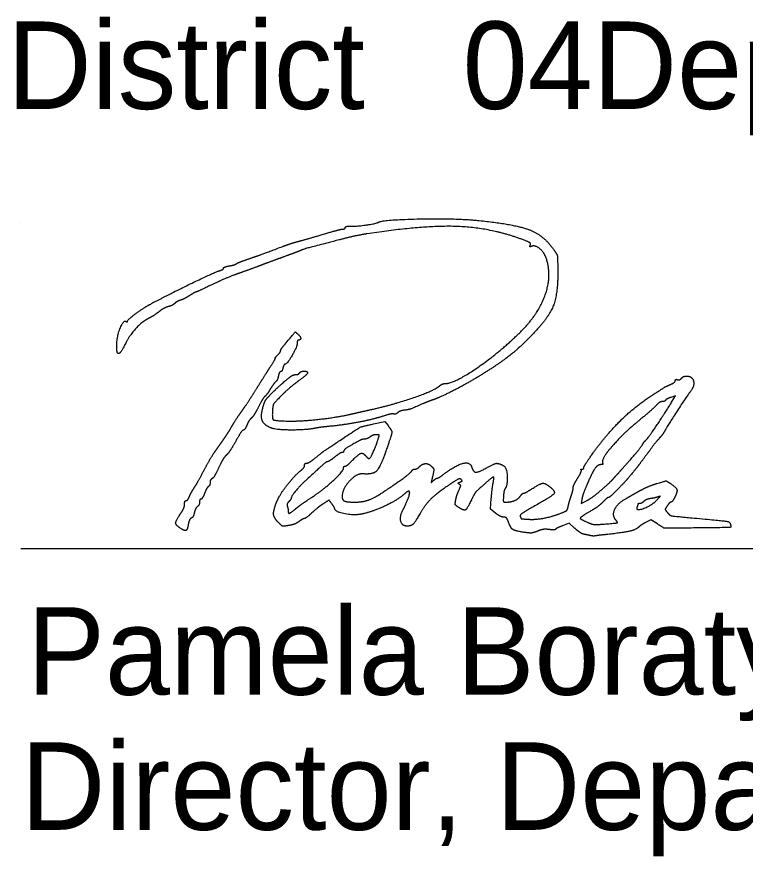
# Model space of a CAD drawing. Extents: x -6.4 to 34, y -4.2 to 22.
# Drawn here: x 24.543 to 25.708, y 7.34 to 8.682 of the extents above; entities that cross this region are included whole.
import ezdxf

# ---------------------------------------------------------------- set-up
doc = ezdxf.new("R2010")
doc.units = 0
for name, color, linetype in [('Default', 7, 'Continuous'), ('SH_Data', 7, 'Continuous'), ('SH_Text', 7, 'Continuous')]:
    doc.layers.add(name, color=color, linetype=linetype)

msp = doc.modelspace()

# ---------------------------------------------------------------- linework, layer by layer
at = {"layer": 'Default'}
for points in [[(25.5912, 8.0673), (25.5966, 8.0762), (25.5893, 8.0736)], [(25.1139, 8.0311), (25.1319, 8.0352), (25.1366, 8.029)], [(25.3089, 7.8883), (25.3005, 7.8946), (25.302, 7.9117)], [(25.4469, 7.9103), (25.4458, 7.9038), (25.4545, 7.9083)], [(25.4358, 7.864), (25.4267, 7.8723), (25.4161, 7.8682)], [(25.5677, 7.871), (25.5571, 7.8778), (25.5487, 7.8733)]]:
    msp.add_lwpolyline(points, dxfattribs=at)
for points in [[(25.0773, 8.3475), (25.0869, 8.3472), (25.1179, 8.3516), (25.1213, 8.3537)], [(25.1213, 8.3537), (25.1281, 8.3579), (25.2451, 8.3602), (25.2795, 8.3568)], [(25.2795, 8.3568), (25.3388, 8.3509), (25.3863, 8.3327), (25.4021, 8.3096)], [(25.0316, 8.3341), (25.0477, 8.3389), (25.0625, 8.3428), (25.0646, 8.3428)], [(25.0646, 8.3428), (25.0666, 8.3428), (25.0683, 8.3439), (25.0683, 8.3452)], [(25.0683, 8.3452), (25.0683, 8.3466), (25.0724, 8.3476), (25.0773, 8.3475)], [(25.352, 8.326), (25.3015, 8.345), (25.1935, 8.349), (25.1031, 8.3352)], [(24.9927, 8.323), (24.998, 8.3243), (25.0155, 8.3293), (25.0316, 8.3341)], [(25.1031, 8.3352), (25.0939, 8.3338), (25.0739, 8.3295), (25.0587, 8.3255)], [(24.9123, 8.2945), (24.927, 8.2996), (24.9335, 8.302), (24.9687, 8.3151)], [(24.9687, 8.3151), (24.9767, 8.3181), (24.9875, 8.3216), (24.9927, 8.323)], [(25.0587, 8.3255), (25.0077, 8.3123), (25.0034, 8.3111), (24.9927, 8.3068)], [(25.3643, 8.3174), (25.3653, 8.3199), (25.3619, 8.3223), (25.352, 8.326)], [(25.3667, 8.3153), (25.3641, 8.3143), (25.3634, 8.315), (25.3643, 8.3174)], [(25.3901, 8.2954), (25.3869, 8.3052), (25.3724, 8.3175), (25.3667, 8.3153)], [(24.9927, 8.3068), (24.9901, 8.3057), (24.9798, 8.3019), (24.9699, 8.2983)], [(25.4021, 8.3096), (25.4071, 8.3024), (25.408, 8.298), (25.4083, 8.2802)], [(24.8829, 8.2839), (24.8879, 8.2848), (24.893, 8.2864), (24.8943, 8.2874)], [(24.8943, 8.2874), (24.8957, 8.2883), (24.9038, 8.2916), (24.9123, 8.2945)], [(24.9699, 8.2983), (24.96, 8.2947), (24.9449, 8.2891), (24.9363, 8.2859)], [(25.3446, 8.1742), (25.3756, 8.2036), (25.3994, 8.2672), (25.3901, 8.2954)], [(24.7563, 8.2224), (24.7866, 8.2386), (24.8602, 8.2742), (24.8685, 8.2767)], [(24.9003, 8.2727), (24.8891, 8.2688), (24.8688, 8.2602), (24.8551, 8.2537)], [(24.8685, 8.2767), (24.8715, 8.2776), (24.8739, 8.2792), (24.8739, 8.2802)], [(24.8739, 8.2802), (24.8739, 8.2813), (24.878, 8.283), (24.8829, 8.2839)], [(24.9363, 8.2859), (24.9278, 8.2826), (24.9116, 8.2767), (24.9003, 8.2727)], [(25.4083, 8.2802), (25.4091, 8.2394), (25.393, 8.1997), (25.3636, 8.1698)], [(24.8551, 8.2537), (24.8415, 8.2472), (24.8298, 8.242), (24.8293, 8.242)], [(24.8193, 8.2363), (24.8144, 8.2332), (24.8077, 8.2298), (24.8044, 8.2288)], [(24.8293, 8.242), (24.8287, 8.242), (24.8242, 8.2394), (24.8193, 8.2363)], [(24.7203, 8.1957), (24.7203, 8.1979), (24.7457, 8.2167), (24.7563, 8.2224)], [(24.7953, 8.2236), (24.7935, 8.2218), (24.7891, 8.2197), (24.7856, 8.2188)], [(24.8044, 8.2288), (24.8012, 8.2278), (24.7971, 8.2254), (24.7953, 8.2236)], [(24.7707, 8.2107), (24.7661, 8.2071), (24.759, 8.2025), (24.7548, 8.2004)], [(24.7856, 8.2188), (24.782, 8.2179), (24.7754, 8.2143), (24.7707, 8.2107)], [(24.7032, 8.1579), (24.7033, 8.1711), (24.7139, 8.1976), (24.718, 8.1951)], [(24.718, 8.1951), (24.7193, 8.1943), (24.7203, 8.1946), (24.7203, 8.1957)], [(24.7548, 8.2004), (24.7444, 8.1951), (24.7245, 8.1742), (24.7183, 8.1621)], [(24.9705, 8.1568), (24.9891, 8.1789), (24.9884, 8.1784), (24.9925, 8.175)], [(24.9925, 8.175), (24.9967, 8.1714), (24.9977, 8.1652), (24.9939, 8.1652)], [(25.2279, 8.0956), (25.242, 8.0956), (25.3101, 8.1415), (25.3446, 8.1742)], [(25.3636, 8.1698), (25.345, 8.1509), (25.3126, 8.126), (25.2821, 8.1072)], [(24.7045, 8.1442), (24.7037, 8.145), (24.7031, 8.1511), (24.7032, 8.1579)], [(24.7183, 8.1621), (24.7117, 8.1492), (24.7064, 8.1423), (24.7045, 8.1442)], [(24.9651, 8.1481), (24.9651, 8.1494), (24.9676, 8.1532), (24.9705, 8.1568)], [(24.9915, 8.1601), (24.9915, 8.1545), (24.9756, 8.1268), (24.9724, 8.1268)], [(24.9939, 8.1652), (24.9926, 8.1652), (24.9915, 8.1629), (24.9915, 8.1601)], [(24.9566, 8.1364), (24.956, 8.1364), (24.9577, 8.1385), (24.9603, 8.1412)], [(24.9603, 8.1412), (24.963, 8.1438), (24.9651, 8.1469), (24.9651, 8.1481)], [(24.9476, 8.1207), (24.9531, 8.1293), (24.9572, 8.1364), (24.9566, 8.1364)], [(24.9724, 8.1268), (24.9713, 8.1268), (24.9698, 8.1241), (24.9689, 8.1208)], [(24.9255, 8.0857), (24.9321, 8.0963), (24.9421, 8.1121), (24.9476, 8.1207)], [(24.9653, 8.1148), (24.9641, 8.1148), (24.9624, 8.1115), (24.9615, 8.1076)], [(24.9689, 8.1208), (24.9681, 8.1175), (24.9665, 8.1148), (24.9653, 8.1148)], [(24.9891, 8.11), (24.9916, 8.11), (24.9943, 8.111), (24.9951, 8.1124)], [(25.0083, 8.1127), (25.0083, 8.1116), (25.0016, 8.1057), (24.9933, 8.0996)], [(24.9951, 8.1124), (24.9969, 8.1153), (25.0083, 8.1156), (25.0083, 8.1127)], [(24.9576, 8.099), (24.9564, 8.0982), (24.9526, 8.093), (24.9492, 8.0876)], [(24.9567, 8.0858), (24.9724, 8.1004), (24.9852, 8.11), (24.9891, 8.11)], [(24.9615, 8.1076), (24.9607, 8.1036), (24.9589, 8.0998), (24.9576, 8.099)], [(24.9933, 8.0996), (24.9851, 8.0935), (24.9726, 8.0826), (24.9655, 8.0755)], [(25.2821, 8.1072), (25.2629, 8.0953), (25.2216, 8.0743), (25.2075, 8.0692)], [(25.5885, 8.0942), (25.5928, 8.0961), (25.5963, 8.099), (25.5963, 8.1005)], [(25.5963, 8.1005), (25.5963, 8.102), (25.5979, 8.1027), (25.5998, 8.102)], [(25.5998, 8.102), (25.6016, 8.1012), (25.6045, 8.1022), (25.6061, 8.1041)], [(25.6061, 8.1041), (25.6076, 8.106), (25.6113, 8.1076), (25.6142, 8.1076)], [(25.6142, 8.1076), (25.6237, 8.1076), (25.6274, 8.0915), (25.62, 8.0825)], [(24.9038, 8.0527), (24.9091, 8.0602), (24.9189, 8.075), (24.9255, 8.0857)], [(24.9354, 8.0512), (24.9381, 8.0642), (24.9443, 8.0742), (24.9567, 8.0858)], [(24.9492, 8.0876), (24.9458, 8.0821), (24.9417, 8.0765), (24.94, 8.0751)], [(25.1079, 8.0536), (25.1449, 8.0618), (25.2111, 8.0847), (25.2197, 8.0922)], [(25.2197, 8.0922), (25.2218, 8.0941), (25.2255, 8.0956), (25.2279, 8.0956)], [(25.5596, 8.0772), (25.5785, 8.0894), (25.5803, 8.0905), (25.5885, 8.0942)], [(24.94, 8.0751), (24.9383, 8.0738), (24.9337, 8.0662), (24.9297, 8.0582)], [(24.9655, 8.0755), (24.9548, 8.0645), (24.9527, 8.0608), (24.9521, 8.0526)], [(25.4649, 7.9846), (25.4872, 8.0155), (25.5322, 8.0595), (25.5596, 8.0772)], [(25.62, 8.0825), (25.6159, 8.0775), (25.583, 8.0271), (25.5799, 8.0209)], [(25.5893, 8.0736), (25.5852, 8.0722), (25.5813, 8.0701), (25.5806, 8.0689)], [(24.9297, 8.0582), (24.9256, 8.0502), (24.9206, 8.0422), (24.9184, 8.0404)], [(25.1919, 8.063), (25.1748, 8.0556), (25.1699, 8.0539), (25.1633, 8.0531)], [(25.2075, 8.0692), (25.2029, 8.0676), (25.1959, 8.0648), (25.1919, 8.063)], [(25.5664, 8.0614), (25.5637, 8.0584), (25.5513, 8.0473), (25.5387, 8.0368)], [(25.5485, 8.0044), (25.5513, 8.0063), (25.5795, 8.0478), (25.5912, 8.0673)], [(25.5753, 8.0668), (25.5731, 8.0668), (25.5691, 8.0643), (25.5664, 8.0614)], [(25.5806, 8.0689), (25.5799, 8.0677), (25.5775, 8.0668), (25.5753, 8.0668)], [(24.8871, 8.0272), (24.8909, 8.0338), (24.8984, 8.0453), (24.9038, 8.0527)], [(24.9507, 8.0243), (24.9403, 8.0282), (24.9332, 8.0407), (24.9354, 8.0512)], [(24.9521, 8.0526), (24.9513, 8.0392), (24.9553, 8.0363), (24.9759, 8.0357)], [(24.9759, 8.0357), (24.9952, 8.0352), (25.053, 8.0413), (25.0743, 8.0461)], [(25.0743, 8.0461), (25.0823, 8.0479), (25.0974, 8.0513), (25.1079, 8.0536)], [(25.1457, 8.0469), (25.1441, 8.0475), (25.136, 8.0458), (25.1277, 8.0431)], [(25.1525, 8.0491), (25.1504, 8.0473), (25.1474, 8.0463), (25.1457, 8.0469)], [(25.1633, 8.0531), (25.1595, 8.0527), (25.1546, 8.0509), (25.1525, 8.0491)], [(24.9184, 8.0404), (24.9162, 8.0386), (24.913, 8.0335), (24.9111, 8.0291)], [(25.1277, 8.0431), (25.1113, 8.0379), (25.0662, 8.0294), (25.0424, 8.0271)], [(25.0599, 8.0047), (25.0916, 8.0257), (25.093, 8.0264), (25.1139, 8.0311)], [(25.5387, 8.0368), (25.5191, 8.0203), (25.5074, 8.0089), (25.4907, 7.99)], [(24.874, 8.0065), (24.8773, 8.0113), (24.8832, 8.0206), (24.8871, 8.0272)], [(24.9054, 8.0212), (24.9041, 8.0212), (24.8987, 8.0133), (24.8934, 8.0036)], [(24.9111, 8.0291), (24.9093, 8.0247), (24.9067, 8.0212), (24.9054, 8.0212)], [(25.022, 8.0245), (25.0083, 8.0214), (24.9588, 8.0213), (24.9507, 8.0243)], [(25.0424, 8.0271), (25.034, 8.0263), (25.0249, 8.0251), (25.022, 8.0245)], [(25.1366, 8.029), (25.1432, 8.0202), (25.1431, 8.0154), (25.1353, 7.9928)], [(25.5799, 8.0209), (25.5781, 8.0174), (25.5742, 8.012), (25.5712, 8.0087)], [(24.8605, 7.9873), (24.8646, 7.9931), (24.8707, 8.0018), (24.874, 8.0065)], [(25.0207, 7.9768), (25.0344, 7.9878), (25.0325, 7.9864), (25.0599, 8.0047)], [(25.0993, 8.0068), (25.0971, 8.0068), (25.0927, 8.0053), (25.0896, 8.0036)], [(25.1081, 8.0103), (25.1055, 8.0083), (25.1016, 8.0068), (25.0993, 8.0068)], [(25.1066, 7.9756), (25.1084, 7.9756), (25.1181, 7.9967), (25.1213, 8.0074)], [(25.118, 8.0139), (25.1151, 8.0138), (25.1106, 8.0122), (25.1081, 8.0103)], [(25.1213, 8.0074), (25.123, 8.0131), (25.1225, 8.0139), (25.118, 8.0139)], [(25.5445, 7.9992), (25.5457, 8.0014), (25.5475, 8.0037), (25.5485, 8.0044)], [(25.5712, 8.0087), (25.5683, 8.0055), (25.5593, 7.9942), (25.5515, 7.9835)], [(24.8934, 8.0036), (24.888, 7.9939), (24.8814, 7.9839), (24.8785, 7.9814)], [(25.0896, 8.0036), (25.0752, 7.9957), (25.0659, 7.9893), (25.0659, 7.9873)], [(25.1353, 7.9928), (25.1251, 7.9629), (25.1131, 7.9498), (25.0971, 7.9512)], [(25.5132, 7.9614), (25.5286, 7.9785), (25.5421, 7.9949), (25.5445, 7.9992)], [(24.8416, 7.9552), (24.8479, 7.967), (24.8564, 7.9815), (24.8605, 7.9873)], [(24.8785, 7.9814), (24.8757, 7.9788), (24.8701, 7.9697), (24.8662, 7.9612)], [(25.0515, 7.978), (25.0465, 7.974), (25.0415, 7.9707), (25.0404, 7.9707)], [(25.0633, 7.9852), (25.0618, 7.9852), (25.0565, 7.9819), (25.0515, 7.978)], [(25.0659, 7.9873), (25.0659, 7.9861), (25.0647, 7.9852), (25.0633, 7.9852)], [(25.0803, 7.9732), (25.0905, 7.9833), (25.097, 7.9851), (25.1019, 7.9792)], [(25.1019, 7.9792), (25.1036, 7.9772), (25.1057, 7.9756), (25.1066, 7.9756)], [(25.4499, 7.9613), (25.4499, 7.9627), (25.4567, 7.9732), (25.4649, 7.9846)], [(25.4907, 7.99), (25.4849, 7.9834), (25.4786, 7.9705), (25.4801, 7.9681)], [(25.5515, 7.9835), (25.5436, 7.9729), (25.5359, 7.9627), (25.5344, 7.9609)], [(24.9981, 7.9571), (25.0011, 7.9595), (25.0035, 7.963), (25.0035, 7.9649)], [(25.0035, 7.9649), (25.0035, 7.9668), (25.005, 7.9684), (25.0069, 7.9684)], [(25.0404, 7.9707), (25.0385, 7.9707), (25.03, 7.9635), (25.0047, 7.9402)], [(25.0069, 7.9684), (25.0088, 7.9684), (25.015, 7.9721), (25.0207, 7.9768)], [(25.0683, 7.9636), (25.0697, 7.9636), (25.0751, 7.9679), (25.0803, 7.9732)], [(25.1871, 7.9627), (25.1921, 7.9676), (25.202, 7.9677), (25.207, 7.9627)], [(25.2251, 7.9501), (25.2453, 7.9653), (25.2681, 7.9709), (25.271, 7.9614)], [(25.2948, 7.961), (25.3068, 7.9677), (25.314, 7.9684), (25.3222, 7.9638)], [(25.4778, 7.966), (25.4715, 7.966), (25.4619, 7.9508), (25.4499, 7.9216)], [(25.4801, 7.9681), (25.4808, 7.9669), (25.4798, 7.966), (25.4778, 7.966)], [(24.8261, 7.9276), (24.8283, 7.9309), (24.8353, 7.9433), (24.8416, 7.9552)], [(24.8662, 7.9612), (24.8623, 7.9526), (24.8576, 7.9447), (24.8557, 7.9436)], [(24.96, 7.9089), (24.9645, 7.9193), (24.9878, 7.9488), (24.9981, 7.9571)], [(25.0199, 7.917), (25.0354, 7.9274), (25.0659, 7.9561), (25.0659, 7.9604)], [(25.0971, 7.9512), (25.0867, 7.9521), (25.0635, 7.9267), (25.0635, 7.9144)], [(25.0659, 7.9604), (25.0659, 7.9621), (25.067, 7.9636), (25.0683, 7.9636)], [(25.1319, 7.9239), (25.1505, 7.9362), (25.1729, 7.9529), (25.1747, 7.9557)], [(25.1747, 7.9557), (25.1757, 7.9574), (25.1781, 7.9588), (25.1799, 7.9588)], [(25.1799, 7.9588), (25.1817, 7.9588), (25.1849, 7.9605), (25.1871, 7.9627)], [(25.207, 7.9627), (25.2101, 7.9596), (25.2104, 7.9571), (25.2083, 7.948)], [(25.271, 7.9614), (25.2735, 7.9538), (25.2815, 7.9537), (25.2948, 7.961)], [(25.3222, 7.9638), (25.3266, 7.9613), (25.3283, 7.9333), (25.3244, 7.9281)], [(25.4402, 7.9445), (25.444, 7.9507), (25.4466, 7.9565), (25.4458, 7.9573)], [(25.4458, 7.9573), (25.445, 7.9581), (25.4456, 7.9588), (25.4471, 7.9588)], [(25.4471, 7.9588), (25.4487, 7.9588), (25.4499, 7.9599), (25.4499, 7.9613)], [(25.4976, 7.9439), (25.5008, 7.9475), (25.5078, 7.9553), (25.5132, 7.9614)], [(25.5344, 7.9609), (25.5211, 7.9444), (25.5166, 7.9393), (25.5047, 7.9271)], [(24.8523, 7.9372), (24.8523, 7.9347), (24.8512, 7.9319), (24.8498, 7.9311)], [(24.8557, 7.9436), (24.8538, 7.9426), (24.8523, 7.9397), (24.8523, 7.9372)], [(25.0047, 7.9402), (24.9956, 7.9318), (24.9819, 7.9148), (24.9819, 7.9118)], [(25.2083, 7.948), (25.2059, 7.9377), (25.206, 7.9372), (25.2098, 7.9407)], [(25.2098, 7.9407), (25.2121, 7.9427), (25.2147, 7.9444), (25.2157, 7.9444)], [(25.2157, 7.9444), (25.2167, 7.9444), (25.2209, 7.9469), (25.2251, 7.9501)], [(25.2538, 7.9423), (25.252, 7.9441), (25.2461, 7.9413), (25.2336, 7.9328)], [(25.2509, 7.9346), (25.2487, 7.936), (25.249, 7.9369), (25.2521, 7.9381)], [(25.2521, 7.9381), (25.2551, 7.9392), (25.2556, 7.9405), (25.2538, 7.9423)], [(25.2949, 7.9382), (25.279, 7.9242), (25.2752, 7.9198), (25.2697, 7.9084)], [(25.305, 7.9366), (25.3068, 7.946), (25.3042, 7.9464), (25.2949, 7.9382)], [(25.4331, 7.9297), (25.4331, 7.9315), (25.4363, 7.9382), (25.4402, 7.9445)], [(25.4775, 7.9251), (25.4855, 7.9319), (25.4945, 7.9404), (25.4976, 7.9439)], [(25.5668, 7.9358), (25.5809, 7.94), (25.5821, 7.94), (25.5879, 7.9362)], [(24.8193, 7.915), (24.8208, 7.9186), (24.8239, 7.9243), (24.8261, 7.9276)], [(24.8498, 7.9311), (24.8485, 7.9302), (24.8456, 7.9253), (24.8436, 7.9201)], [(25.0835, 7.906), (25.0965, 7.906), (25.1156, 7.913), (25.1319, 7.9239)], [(25.2336, 7.9328), (25.2138, 7.9194), (25.1966, 7.9023), (25.1883, 7.888)], [(25.2451, 7.9092), (25.2459, 7.9133), (25.2482, 7.9204), (25.2502, 7.9248)], [(25.2502, 7.9248), (25.2531, 7.9311), (25.2532, 7.9332), (25.2509, 7.9346)], [(25.302, 7.9117), (25.3028, 7.9211), (25.3041, 7.9323), (25.305, 7.9366)], [(25.3244, 7.9281), (25.3232, 7.9265), (25.3218, 7.9208), (25.3215, 7.9155)], [(25.354, 7.9204), (25.3552, 7.9204), (25.3613, 7.9236), (25.3675, 7.9276)], [(25.3957, 7.9305), (25.4054, 7.9229), (25.3986, 7.915), (25.367, 7.8973)], [(25.3675, 7.9276), (25.3805, 7.9358), (25.3881, 7.9366), (25.3957, 7.9305)], [(25.4296, 7.9156), (25.4316, 7.9215), (25.4332, 7.9279), (25.4331, 7.9297)], [(25.4545, 7.9083), (25.4592, 7.9107), (25.4696, 7.9183), (25.4775, 7.9251)], [(25.5047, 7.9271), (25.4972, 7.9194), (25.4902, 7.9132), (25.4891, 7.9132)], [(25.5375, 7.9231), (25.5455, 7.9276), (25.5586, 7.9333), (25.5668, 7.9358)], [(25.5879, 7.9362), (25.5975, 7.9299), (25.6, 7.9225), (25.5953, 7.9135)], [(24.814, 7.9084), (24.8153, 7.9084), (24.8177, 7.9113), (24.8193, 7.915)], [(24.8377, 7.9108), (24.8365, 7.9108), (24.8355, 7.9087), (24.8355, 7.9062)], [(24.8436, 7.9201), (24.8415, 7.915), (24.8388, 7.9108), (24.8377, 7.9108)], [(24.9819, 7.9118), (24.9819, 7.911), (24.9802, 7.9087), (24.9782, 7.9067)], [(24.9883, 7.8946), (24.9959, 7.9007), (25.0011, 7.9045), (25.0199, 7.917)], [(25.0635, 7.9144), (25.0635, 7.9093), (25.0714, 7.906), (25.0835, 7.906)], [(25.1639, 7.9197), (25.1543, 7.9106), (25.1156, 7.8918), (25.0971, 7.8873)], [(25.161, 7.894), (25.1651, 7.9016), (25.1715, 7.9179), (25.1715, 7.9206)], [(25.1715, 7.9206), (25.1715, 7.9237), (25.1676, 7.9232), (25.1639, 7.9197)], [(25.3215, 7.9155), (25.321, 7.908), (25.3217, 7.906), (25.3248, 7.906)], [(25.3248, 7.906), (25.3331, 7.906), (25.3451, 7.9108), (25.3484, 7.9155)], [(25.3484, 7.9155), (25.3503, 7.9182), (25.3528, 7.9204), (25.354, 7.9204)], [(25.4249, 7.8985), (25.4255, 7.9019), (25.4277, 7.9096), (25.4296, 7.9156)], [(25.4499, 7.9216), (25.4488, 7.9189), (25.4474, 7.9138), (25.4469, 7.9103)], [(25.4891, 7.9132), (25.488, 7.9132), (25.4842, 7.91), (25.4806, 7.9062)], [(25.5009, 7.8777), (25.4949, 7.8851), (25.5046, 7.9049), (25.518, 7.9121)], [(25.518, 7.9121), (25.5208, 7.9136), (25.5296, 7.9186), (25.5375, 7.9231)], [(25.5569, 7.9117), (25.5531, 7.9112), (25.5481, 7.9091), (25.5459, 7.9072)], [(25.5687, 7.9144), (25.5661, 7.9134), (25.5608, 7.9122), (25.5569, 7.9117)], [(25.5663, 7.9089), (25.5718, 7.9145), (25.5724, 7.9158), (25.5687, 7.9144)], [(25.5953, 7.9135), (25.5932, 7.9093), (25.5905, 7.906), (25.5893, 7.906)], [(24.8057, 7.8885), (24.8089, 7.8932), (24.8115, 7.8996), (24.8115, 7.9027)], [(24.8115, 7.9027), (24.8115, 7.9058), (24.8126, 7.9084), (24.814, 7.9084)], [(24.8321, 7.8989), (24.8302, 7.8973), (24.8279, 7.8928), (24.8271, 7.8888)], [(24.8355, 7.9062), (24.8355, 7.9038), (24.834, 7.9005), (24.8321, 7.8989)], [(24.9617, 7.8732), (24.9541, 7.8808), (24.9535, 7.8936), (24.96, 7.9089)], [(24.9782, 7.9067), (24.9761, 7.9046), (24.9751, 7.9014), (24.9758, 7.8994)], [(24.9758, 7.8994), (24.9765, 7.8975), (24.9771, 7.8944), (24.9771, 7.8926)], [(25.0356, 7.9048), (25.0274, 7.8994), (25.0249, 7.8974), (25.0137, 7.8874)], [(25.0469, 7.9034), (25.0425, 7.9092), (25.0424, 7.9092), (25.0356, 7.9048)], [(25.0515, 7.896), (25.0514, 7.8969), (25.0494, 7.9002), (25.0469, 7.9034)], [(25.2497, 7.8976), (25.2448, 7.9009), (25.244, 7.9029), (25.2451, 7.9092)], [(25.2697, 7.9084), (25.2631, 7.8947), (25.2582, 7.8921), (25.2497, 7.8976)], [(25.367, 7.8973), (25.3538, 7.8898), (25.3475, 7.885), (25.3484, 7.8828)], [(25.4122, 7.8878), (25.421, 7.8912), (25.4239, 7.8937), (25.4249, 7.8985)], [(25.4806, 7.9062), (25.4769, 7.9024), (25.4688, 7.8963), (25.4626, 7.8926)], [(25.5349, 7.8978), (25.5324, 7.8913), (25.5579, 7.9002), (25.5663, 7.9089)], [(25.5363, 7.9025), (25.5363, 7.902), (25.5357, 7.8999), (25.5349, 7.8978)], [(25.5391, 7.9036), (25.5376, 7.9036), (25.5363, 7.9031), (25.5363, 7.9025)], [(25.5459, 7.9072), (25.5437, 7.9052), (25.5407, 7.9036), (25.5391, 7.9036)], [(25.5835, 7.9001), (25.58, 7.8948), (25.58, 7.8939), (25.5838, 7.8892)], [(25.5893, 7.906), (25.5882, 7.906), (25.5856, 7.9033), (25.5835, 7.9001)], [(24.804, 7.8648), (24.797, 7.8696), (24.7975, 7.8763), (24.8057, 7.8885)], [(24.8271, 7.8888), (24.8262, 7.8849), (24.8241, 7.8811), (24.8223, 7.8804)], [(24.9771, 7.8926), (24.9771, 7.8877), (24.9806, 7.8883), (24.9883, 7.8946)], [(25.0137, 7.8874), (25.0089, 7.8831), (25.004, 7.8796), (25.0029, 7.8796)], [(25.0971, 7.8873), (25.0843, 7.8842), (25.0517, 7.8904), (25.0515, 7.896)], [(25.1677, 7.8676), (25.1593, 7.8676), (25.1553, 7.8834), (25.161, 7.894)], [(25.1883, 7.888), (25.1801, 7.8738), (25.1738, 7.8676), (25.1677, 7.8676)], [(25.3219, 7.882), (25.3193, 7.882), (25.3134, 7.8848), (25.3089, 7.8883)], [(25.3623, 7.8785), (25.3729, 7.8779), (25.399, 7.8828), (25.4122, 7.8878)], [(25.4626, 7.8926), (25.4446, 7.8822), (25.4436, 7.8789), (25.4565, 7.8734)], [(25.5838, 7.8892), (25.5875, 7.8847), (25.5925, 7.8837), (25.6263, 7.8805)], [(24.8177, 7.8712), (24.8159, 7.8615), (24.8117, 7.8595), (24.804, 7.8648)], [(24.8223, 7.8804), (24.8206, 7.8798), (24.8185, 7.8756), (24.8177, 7.8712)], [(24.9779, 7.8685), (24.9692, 7.8672), (24.9671, 7.8678), (24.9617, 7.8732)], [(24.9944, 7.8748), (24.9909, 7.8722), (24.9834, 7.8694), (24.9779, 7.8685)], [(25.0029, 7.8796), (25.0018, 7.8796), (24.998, 7.8774), (24.9944, 7.8748)], [(25.3294, 7.8742), (25.3275, 7.8793), (25.325, 7.882), (25.3219, 7.882)], [(25.3548, 7.8576), (25.3397, 7.86), (25.3329, 7.8645), (25.3294, 7.8742)], [(25.3484, 7.8828), (25.3497, 7.8794), (25.3504, 7.8792), (25.3623, 7.8785)], [(25.4565, 7.8734), (25.4634, 7.8704), (25.4698, 7.8699), (25.4833, 7.8709)], [(25.4833, 7.8709), (25.5029, 7.8725), (25.5046, 7.8732), (25.5009, 7.8777)], [(25.5487, 7.8733), (25.5441, 7.8708), (25.5388, 7.8673), (25.537, 7.8654)], [(25.6143, 7.8645), (25.5786, 7.8642), (25.5783, 7.8642), (25.5677, 7.871)], [(25.6263, 7.8805), (25.6754, 7.876), (25.6837, 7.8744), (25.6846, 7.8697)], [(25.3759, 7.8596), (25.3689, 7.8568), (25.3633, 7.8563), (25.3548, 7.8576)], [(25.3947, 7.8621), (25.389, 7.8629), (25.3817, 7.8619), (25.3759, 7.8596)], [(25.4048, 7.8625), (25.4044, 7.8616), (25.3999, 7.8614), (25.3947, 7.8621)], [(25.4161, 7.8682), (25.4103, 7.8659), (25.4052, 7.8633), (25.4048, 7.8625)], [(25.4505, 7.8545), (25.4475, 7.8551), (25.4409, 7.8594), (25.4358, 7.864)], [(25.537, 7.8654), (25.5332, 7.8617), (25.5117, 7.8568), (25.4883, 7.8544)], [(25.6846, 7.8697), (25.6854, 7.8654), (25.6835, 7.8653), (25.6143, 7.8645)], [(25.4607, 7.8524), (25.4581, 7.8529), (25.4535, 7.8539), (25.4505, 7.8545)], [(25.4691, 7.8521), (25.4672, 7.8517), (25.4634, 7.8518), (25.4607, 7.8524)], [(25.4883, 7.8544), (25.4798, 7.8535), (25.4711, 7.8525), (25.4691, 7.8521)]]:
    msp.add_open_spline(points, degree=2, dxfattribs=at)
at = {"layer": 'SH_Data'}
for p, q in [((24.5497, 8.354), (24.5497, 8.354)), ((24.5497, 7.8317), (28.0497, 7.8317))]:
    msp.add_line(p, q, dxfattribs=at)

# ---------------------------------------------------------------- texts
at = {"layer": 'SH_Text'}
for s, p in [('District       Deputy Director', (24.5279, 8.535)), ('              04', (24.5279, 8.535)), ('Pamela Boratyn', (24.5594, 7.5978)), ('Director, Department of Transportation', (24.5497, 7.3817))]:
    msp.add_text(s, height=0.14, dxfattribs=at).set_placement(p)

doc.saveas('drawing.dxf')
